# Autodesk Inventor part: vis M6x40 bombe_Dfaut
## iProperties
Created: 2006-03
Part Number: vis M6x40 bombe_Dfaut
Document SubType Name: Modeling
Designer: Flavien MARTY
Author: Flavien MARTY
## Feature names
1. Base1
